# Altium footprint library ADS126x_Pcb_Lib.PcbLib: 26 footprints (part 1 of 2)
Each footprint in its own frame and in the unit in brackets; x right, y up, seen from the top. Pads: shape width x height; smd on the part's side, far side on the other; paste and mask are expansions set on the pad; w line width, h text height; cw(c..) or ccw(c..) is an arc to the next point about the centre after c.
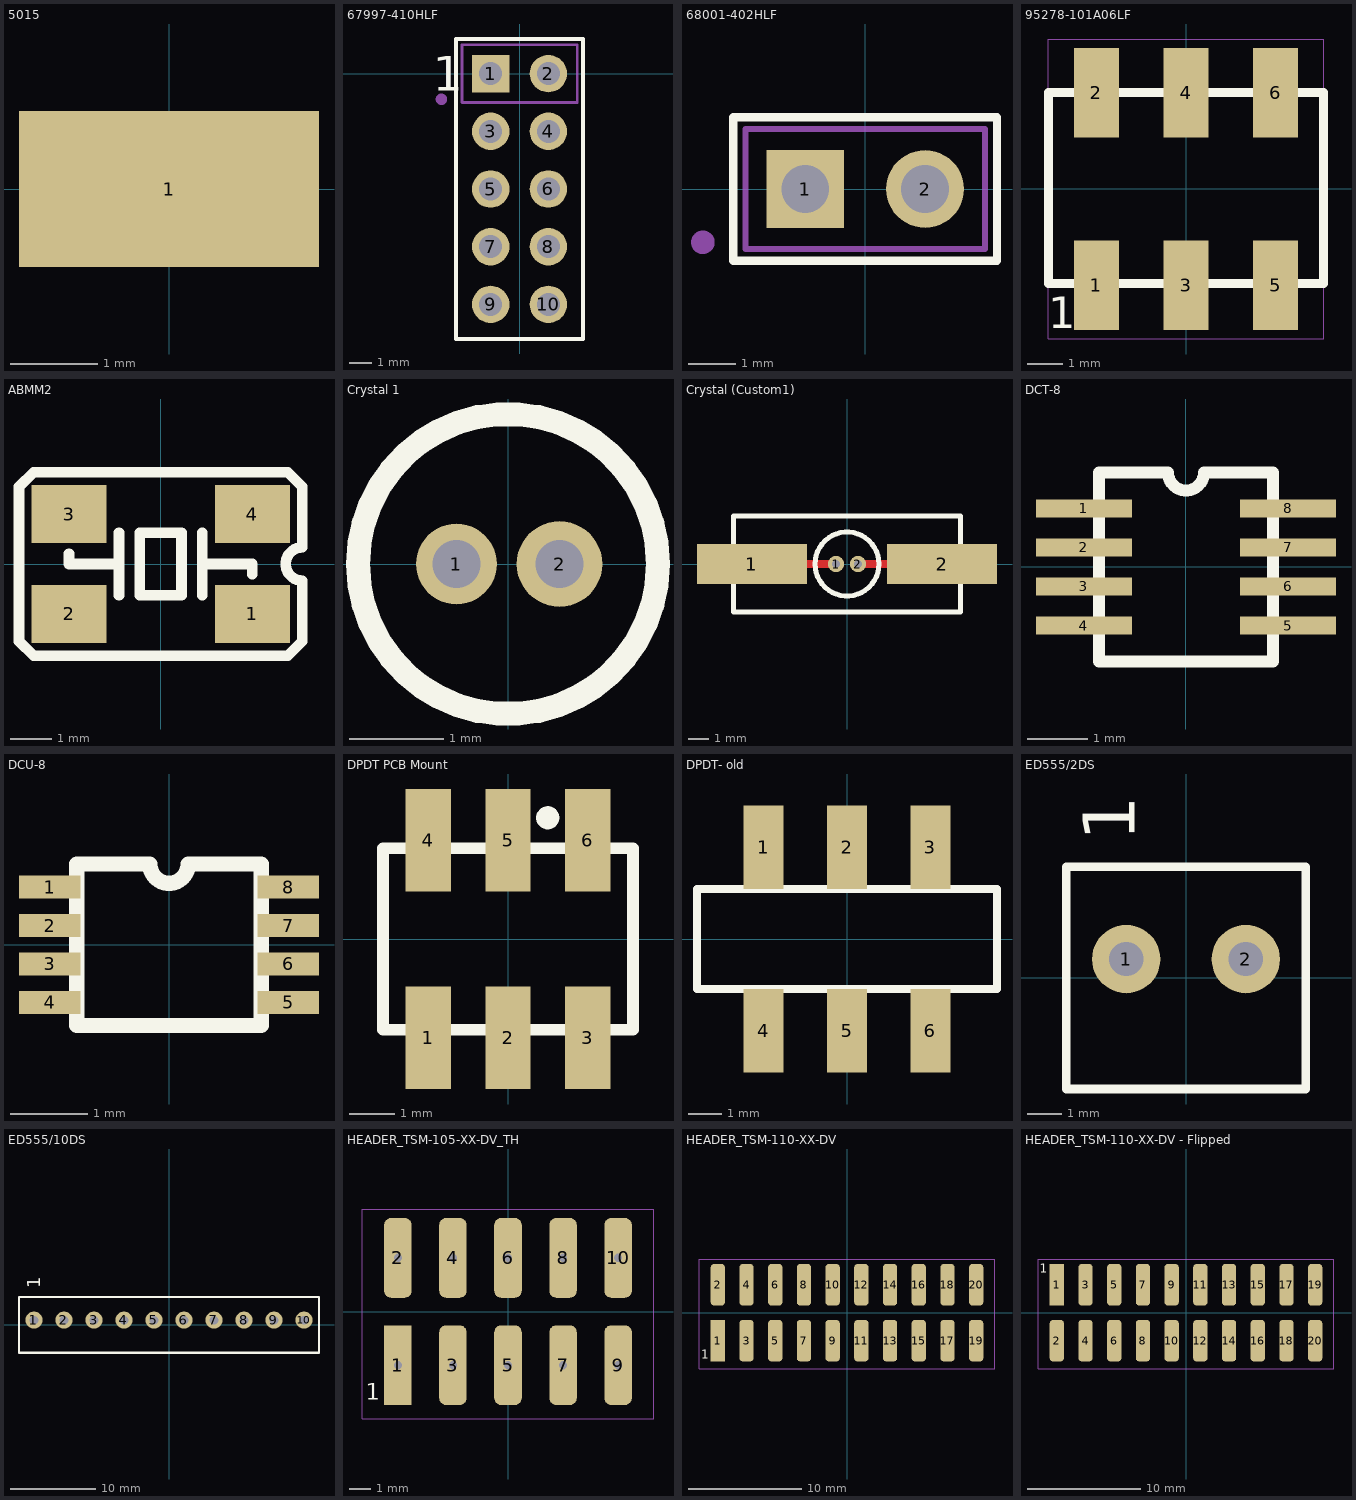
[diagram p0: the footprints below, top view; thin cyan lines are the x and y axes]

## 5015 [mil]
pads (1):
  rect 135x70 smd: 1(0,0)

## 67997-410HLF [mm] "FCI HEADER,100mil, 2POS 1x2"
height 8.382
pads (10):
  rect 1.65x1.65 hole 1.016 mask+0: 1(-1.27,0)
  round 1.65 hole 1.016 mask+0: 2(1.27,0) 3(-1.27,-2.54) 4(1.27,-2.54) 5(-1.27,-5.08) 6(1.27,-5.08) 7(-1.27,-7.62) 8(1.27,-7.62) 9(-1.27,-10.16) 10(1.27,-10.16)
Top Overlay:
  lines w0.178: -2.794,-11.684 2.794,-11.684 2.794,1.524 -2.794,1.524 -2.794,-11.684
  text "1" at -3.81,-0.762 h1.52
M5 Assembly Top:
  circle w0.25: c-3.44,-1.13 r0.125
  lines w0.127: -2.54,-1.27 2.54,-1.27 2.54,1.27 -2.54,1.27 -2.54,-1.27
  text ".Designator" at -1.524,-0.508 h1.02
3D body: height 8.38, standoff -2.54, extent -2.54,-11.43 2.54,-8.89
3D body: height 8.38, standoff -2.54, extent -2.54,-8.89 2.54,-6.35
3D body: height 8.38, standoff -2.54, extent -2.54,-6.35 2.54,-3.81
3D body: height 8.38, standoff -2.54, extent -2.54,-1.27 2.54,1.27
3D body: height 8.38, standoff -2.54, extent -2.54,-3.81 2.54,-1.27

## 68001-402HLF [mm] "FCI HEADER,100mil, 2POS 1x2"
height 8.382
pads (2):
  rect 1.65x1.65 hole 1.016 mask+0: 1(-1.27,0)
  round 1.65 hole 1.016 mask+0: 2(1.27,0)
Top Overlay:
  lines w0.178: -2.794,-1.524 2.794,-1.524 2.794,1.524 -2.794,1.524 -2.794,-1.524
  text ".Designator" at -2.794,1.905 h1.52
M5 Assembly Top:
  circle w0.25: c-3.44,-1.13 r0.125
  lines w0.127: -2.54,-1.27 -2.54,1.27 2.54,1.27 2.54,-1.27 -2.54,-1.27
  text ".Designator" at -1.524,-0.508 h1.02
3D body: height 8.38, standoff -2.54, extent -2.54,-1.27 2.54,1.27

## 95278-101A06LF [mm]
pads (6):
  rect 1.27x2.54 smd: 1(-2.54,-2.73) 2(-2.54,2.73) 3(0,-2.73) 4(0,2.73) 5(2.54,-2.73) 6(2.54,2.73)
Top Overlay:
  lines w0.254: -3.9,-2.68 -3.9,2.73 3.9,2.73 3.9,-2.68 -3.9,-2.68
  text "1" at -3.9,-4.25 h1.52
M15  Courtyards Top:
  lines w0.028: -3.9,4.25 -3.9,-4.25 3.9,-4.25 3.9,4.25 ; -3.9,4.25 3.9,4.25 ; -3.9,4.25 3.9,4.25
  text "1" at -3.25,-3.5 h1.52
3D body: height 3.8, standoff 0, extent -3.81,-2.415 3.81,2.415
3D body: height 9.7, standoff 0, extent 2.23,-1.58 2.85,-0.96
3D body: height 9.7, standoff 0, extent 2.23,0.96 2.85,1.58
3D body: height 9.7, standoff 0, extent -2.85,0.96 -2.23,1.58
3D body: height 9.7, standoff 0, extent -2.85,-1.58 -2.23,-0.96
3D body: height 9.7, standoff 0, extent -0.31,-1.58 0.31,-0.96
3D body: height 9.7, standoff 0, extent -0.31,0.96 0.31,1.58

## ABMM2 [mm]
pads (4):
  rect 1.8x1.4 smd: 1(2.2,-1.2) 2(-2.2,-1.2) 3(-2.2,1.2) 4(2.2,1.2)
Top Overlay:
  lines w0.254: -2.2,0.25 -2.2,0 -1,0 ; -1,-0.75 -1,0.75 ; 1,-0.75 1,0.75 ; 1,0 2.2,0 2.2,-0.25 ; -3.4,-1.85 -3.4,1.85 -3.05,2.2 3.05,2.2 3.4,1.85 3.4,0.4 ccw(c3.4,0) 3.4,-0.4 3.4,-1.85 3.05,-2.2 -3.05,-2.2 -3.4,-1.85 ; -0.5,-0.75 -0.5,0.75 0.5,0.75 0.5,-0.75 -0.5,-0.75
3D body: height 0.6, standoff 0, extent -3.404,-2.21 3.429,2.21
3D body: height 1.2, standoff 0, extent -3.277,-2.083 3.277,2.083

## Crystal 1 [mil]
pads (2):
  round 34 hole 20: 1(-21.65,0)
  round 36 hole 20: 2(21.65,0)
Top Overlay:
  circle w10: c0,0 r62.99

## Crystal (Custom1) [mm]
pads (4):
  rect 5.5x2 smd: 1(-4.75,0) 2(4.75,0)
  round 0.813 hole 0.406: 1(-0.55,0) 2(0.55,0)
Top Layer:
  lines w0.381: -4.75,0 -0.55,0 ; 0.55,0 4.75,0
Top Overlay:
  circle w0.254: c0,0 r1.6
  lines w0.254: -5.675,-2.4 -5.675,2.4 5.675,2.4 5.675,-2.4 -5.675,-2.4

## DCT-8 [mm]
height 1.3
pads (8):
  rect 1.6x0.3 smd: 1(-1.7,0.975) 2(-1.7,0.325) 3(-1.7,-0.325) 4(-1.7,-0.975) 5(1.7,-0.975) 6(1.7,-0.325) 7(1.7,0.325) 8(1.7,0.975)
Top Overlay:
  lines w0.2: -1.45,-1.575 -1.45,1.575 -0.3,1.575 ccw(c0,1.575) 0.3,1.575 1.45,1.575 1.45,-1.575 -1.45,-1.575
3D body: height 1.3, standoff 0.01, extent -1.44,1.4 1.44,1.574
3D body: height 1.3, standoff 0, extent -1.45,-1.575 1.45,1.575

## DCU-8 [mm]
height 0.9
pads (8):
  rect 0.8x0.3 smd: 1(-1.55,0.75) 2(-1.55,0.25) 3(-1.55,-0.25) 4(-1.55,-0.75) 5(1.55,-0.75) 6(1.55,-0.25) 7(1.55,0.25) 8(1.55,0.75)
Top Overlay:
  lines w0.2: -1.2,-1.05 -1.2,1.05 -0.25,1.05 ccw(c0,1.05) 0.25,1.05 1.2,1.05 1.2,-1.05 -1.2,-1.05
3D body: height 0.9, standoff 0, extent -1.2,-1.05 1.2,1.05
3D body: height 0.9, standoff 0.01, extent -1.19,0.94 1.19,1.04
3D body: height 0.12, standoff 0, extent -1.55,0.625 -1.2,0.875
3D body: height 0.12, standoff 0, extent -1.55,0.125 -1.2,0.375
3D body: height 0.12, standoff 0, extent -1.55,-0.375 -1.2,-0.125
3D body: height 0.12, standoff 0, extent -1.55,-0.875 -1.2,-0.625
3D body: height 0.12, standoff 0, extent 1.2,-0.875 1.55,-0.625
3D body: height 0.12, standoff 0, extent 1.2,-0.375 1.55,-0.125
3D body: height 0.12, standoff 0, extent 1.2,0.125 1.55,0.375
3D body: height 0.12, standoff 0, extent 1.2,0.625 1.55,0.875

## DPDT PCB Mount [mm]
pads (6):
  rect 1x2.25 smd: 1(-1.75,-2.175) 2(0,-2.175) 3(1.75,-2.175) 4(-1.75,2.175) 5(0,2.175) 6(1.75,2.175)
Top Overlay:
  circle w0.254: c0.875,2.667 r0.127
  lines w0.254: -2.75,-2 -2.75,2 2.75,2 2.75,-2 -2.75,-2
3D body: height 2.5, standoff 0, extent -2.8,-2 2.75,2
3D body: height 2.7, standoff 0, extent 0,-0.8 1,0.7
3D body: height 2.51, standoff 0, extent -1,-0.8 0,0.7

## DPDT- old [mm]
pads (6):
  rect 1.2x2.5 smd: 1(-2.5,2.75) 2(0,2.75) 3(2.5,2.75) 4(-2.5,-2.75) 5(0,-2.75) 6(2.5,-2.75)
Top Overlay:
  lines w0.254: -4.5,-1.5 4.5,-1.5 4.5,1.5 -4.5,1.5 -4.5,-1.5
3D body: height 3.5, standoff 0, extent -4.5,-1.5 4.5,1.5
3D body: height 5.5, standoff 2, extent -1.3,-0.75 0.2,0.75

## ED555/2DS [mm]
pads (2):
  round 2 hole 1: 1(-1.75,0.55) 2(1.75,0.55)
Top Overlay:
  lines w0.254: -3.5,-3.25 3.5,-3.25 3.5,3.25 -3.5,3.25 -3.5,-3.25
  text "1" at -1.5,4 h1.52
3D body: height 0, standoff -3.5, extent 1.304,-0.449 2.2,0.449
3D body: height 0, standoff -3.5, extent -2.196,-0.449 -1.3,0.449
3D body: height 8.2, standoff 0, extent -3.5,-3.25 3.5,3.25

## ED555/10DS [mm]
pads (10):
  round 2 hole 1: 1(-15.75,0.55) 2(-12.25,0.55) 3(-8.75,0.55) 4(-5.25,0.55) 5(-1.75,0.55) 6(1.75,0.55) 7(5.25,0.55) 8(8.75,0.55) 9(12.25,0.55) 10(15.75,0.55)
Top Overlay:
  lines w0.254: -17.5,-3.25 17.5,-3.25 17.5,3.25 -17.5,3.25 -17.5,-3.25
  text "1" at -15,4.25 h1.52
3D body: height 0, standoff -3.5, extent 15.304,0.101 16.2,0.999
3D body: height 0, standoff -3.5, extent 11.804,0.101 12.7,0.999
3D body: height 0, standoff -3.5, extent 8.304,0.101 9.2,0.999
3D body: height 0, standoff -3.5, extent 4.804,0.101 5.7,0.999
3D body: height 0, standoff -3.5, extent 1.304,0.101 2.2,0.999
3D body: height 0, standoff -3.5, extent -2.196,0.101 -1.3,0.999
3D body: height 0, standoff -3.5, extent -5.696,0.101 -4.8,0.999
3D body: height 0, standoff -3.5, extent -9.196,0.101 -8.3,0.999
3D body: height 0, standoff -3.5, extent -12.696,0.101 -11.8,0.999
3D body: height 0, standoff -3.5, extent -16.196,0.101 -15.3,0.999
3D body: height 8.2, standoff 0, extent -17.5,-3.25 17.5,3.25

## HEADER_TSM-105-XX-DV_TH [mil]
pads (10):
  rect 50x145 hole 15: 1(-200.1,-97.2)
  rrect50% 50x145 hole 15: 2(-200.1,97.8) 3(-100.1,-97.2) 4(-100.1,97.8) 5(-0.1,-97.2) 6(-0.1,97.8) 7(99.9,-97.2) 8(99.9,97.8) 9(199.9,-97.2) 10(199.9,97.8)
Top Overlay:
  text "1" at -258.17,-159.7 h30
M15  Courtyards Top:
  lines w1.1: -265.1,-194.2 264.9,-194.2 264.9,185.8 -265.1,185.8 -265.1,-194.2
  text "1" at -258.17,-159.7 h30

## HEADER_TSM-110-XX-DV [mil]
pads (20):
  rect 50x145 smd: 1(-450.1,-97.2)
  rrect50% 50x145 smd: 2(-450.1,97.8) 3(-350.1,-97.2) 4(-350.1,97.8) 5(-250.1,-97.2) 6(-250.1,97.8) 7(-150.1,-97.2) 8(-150.1,97.8) 9(-50.1,-97.2) 10(-50.1,97.8) 11(49.9,-97.2) 12(49.9,97.8) 13(149.9,-97.2) 14(149.9,97.8) 15(249.9,-97.2) 16(249.9,97.8) 17(349.9,-97.2) 18(349.9,97.8) 19(449.9,-97.2) 20(449.9,97.8)
Top Overlay:
  text "1" at -508.17,-159.7 h30
M15  Courtyards Top:
  lines w1.1: -515.1,-194.2 514.9,-194.2 514.9,185.8 -515.1,185.8 -515.1,-194.2
  text "1" at -508.17,-159.7 h30

## HEADER_TSM-110-XX-DV - Flipped [mil]
pads (20):
  rect 50x145 smd: 1(-450.1,97.8)
  rrect50% 50x145 smd: 2(-450.1,-97.2) 3(-350.1,97.8) 4(-350.1,-97.2) 5(-250.1,97.8) 6(-250.1,-97.2) 7(-150.1,97.8) 8(-150.1,-97.2) 9(-50.1,97.8) 10(-50.1,-97.2) 11(49.9,97.8) 12(49.9,-97.2) 13(149.9,97.8) 14(149.9,-97.2) 15(249.9,97.8) 16(249.9,-97.2) 17(349.9,97.8) 18(349.9,-97.2) 19(449.9,97.8) 20(449.9,-97.2)
Top Overlay:
  text "1" at -510,140 h30
M15  Courtyards Top:
  lines w1.1: -515.1,-194.2 514.9,-194.2 514.9,185.8 -515.1,185.8 -515.1,-194.2
  text "1" at -510,140 h30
